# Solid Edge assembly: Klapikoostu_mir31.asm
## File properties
Author: Türk
Template: Iso Assembly.asm
Last saved by: Türk
Revision: 3
Application: Solid Edge
Username: Türk
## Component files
Klapipuks.par
Klapi vedru_mir1.par
Klapp.par
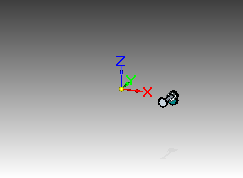
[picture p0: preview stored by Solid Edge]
